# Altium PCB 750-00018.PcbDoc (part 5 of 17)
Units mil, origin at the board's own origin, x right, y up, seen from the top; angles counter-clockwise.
Board outline 7086.64 x 6299.21 mil, 8 copper layers (Top Layer, L2, L3, L4, L5, L6, L7, Bottom Layer), stack 60.6 mil thick; 1356 components, 1054 nets, 4851 pads, 4296 vias.
Unrouted connection lines stored in the file: 12.
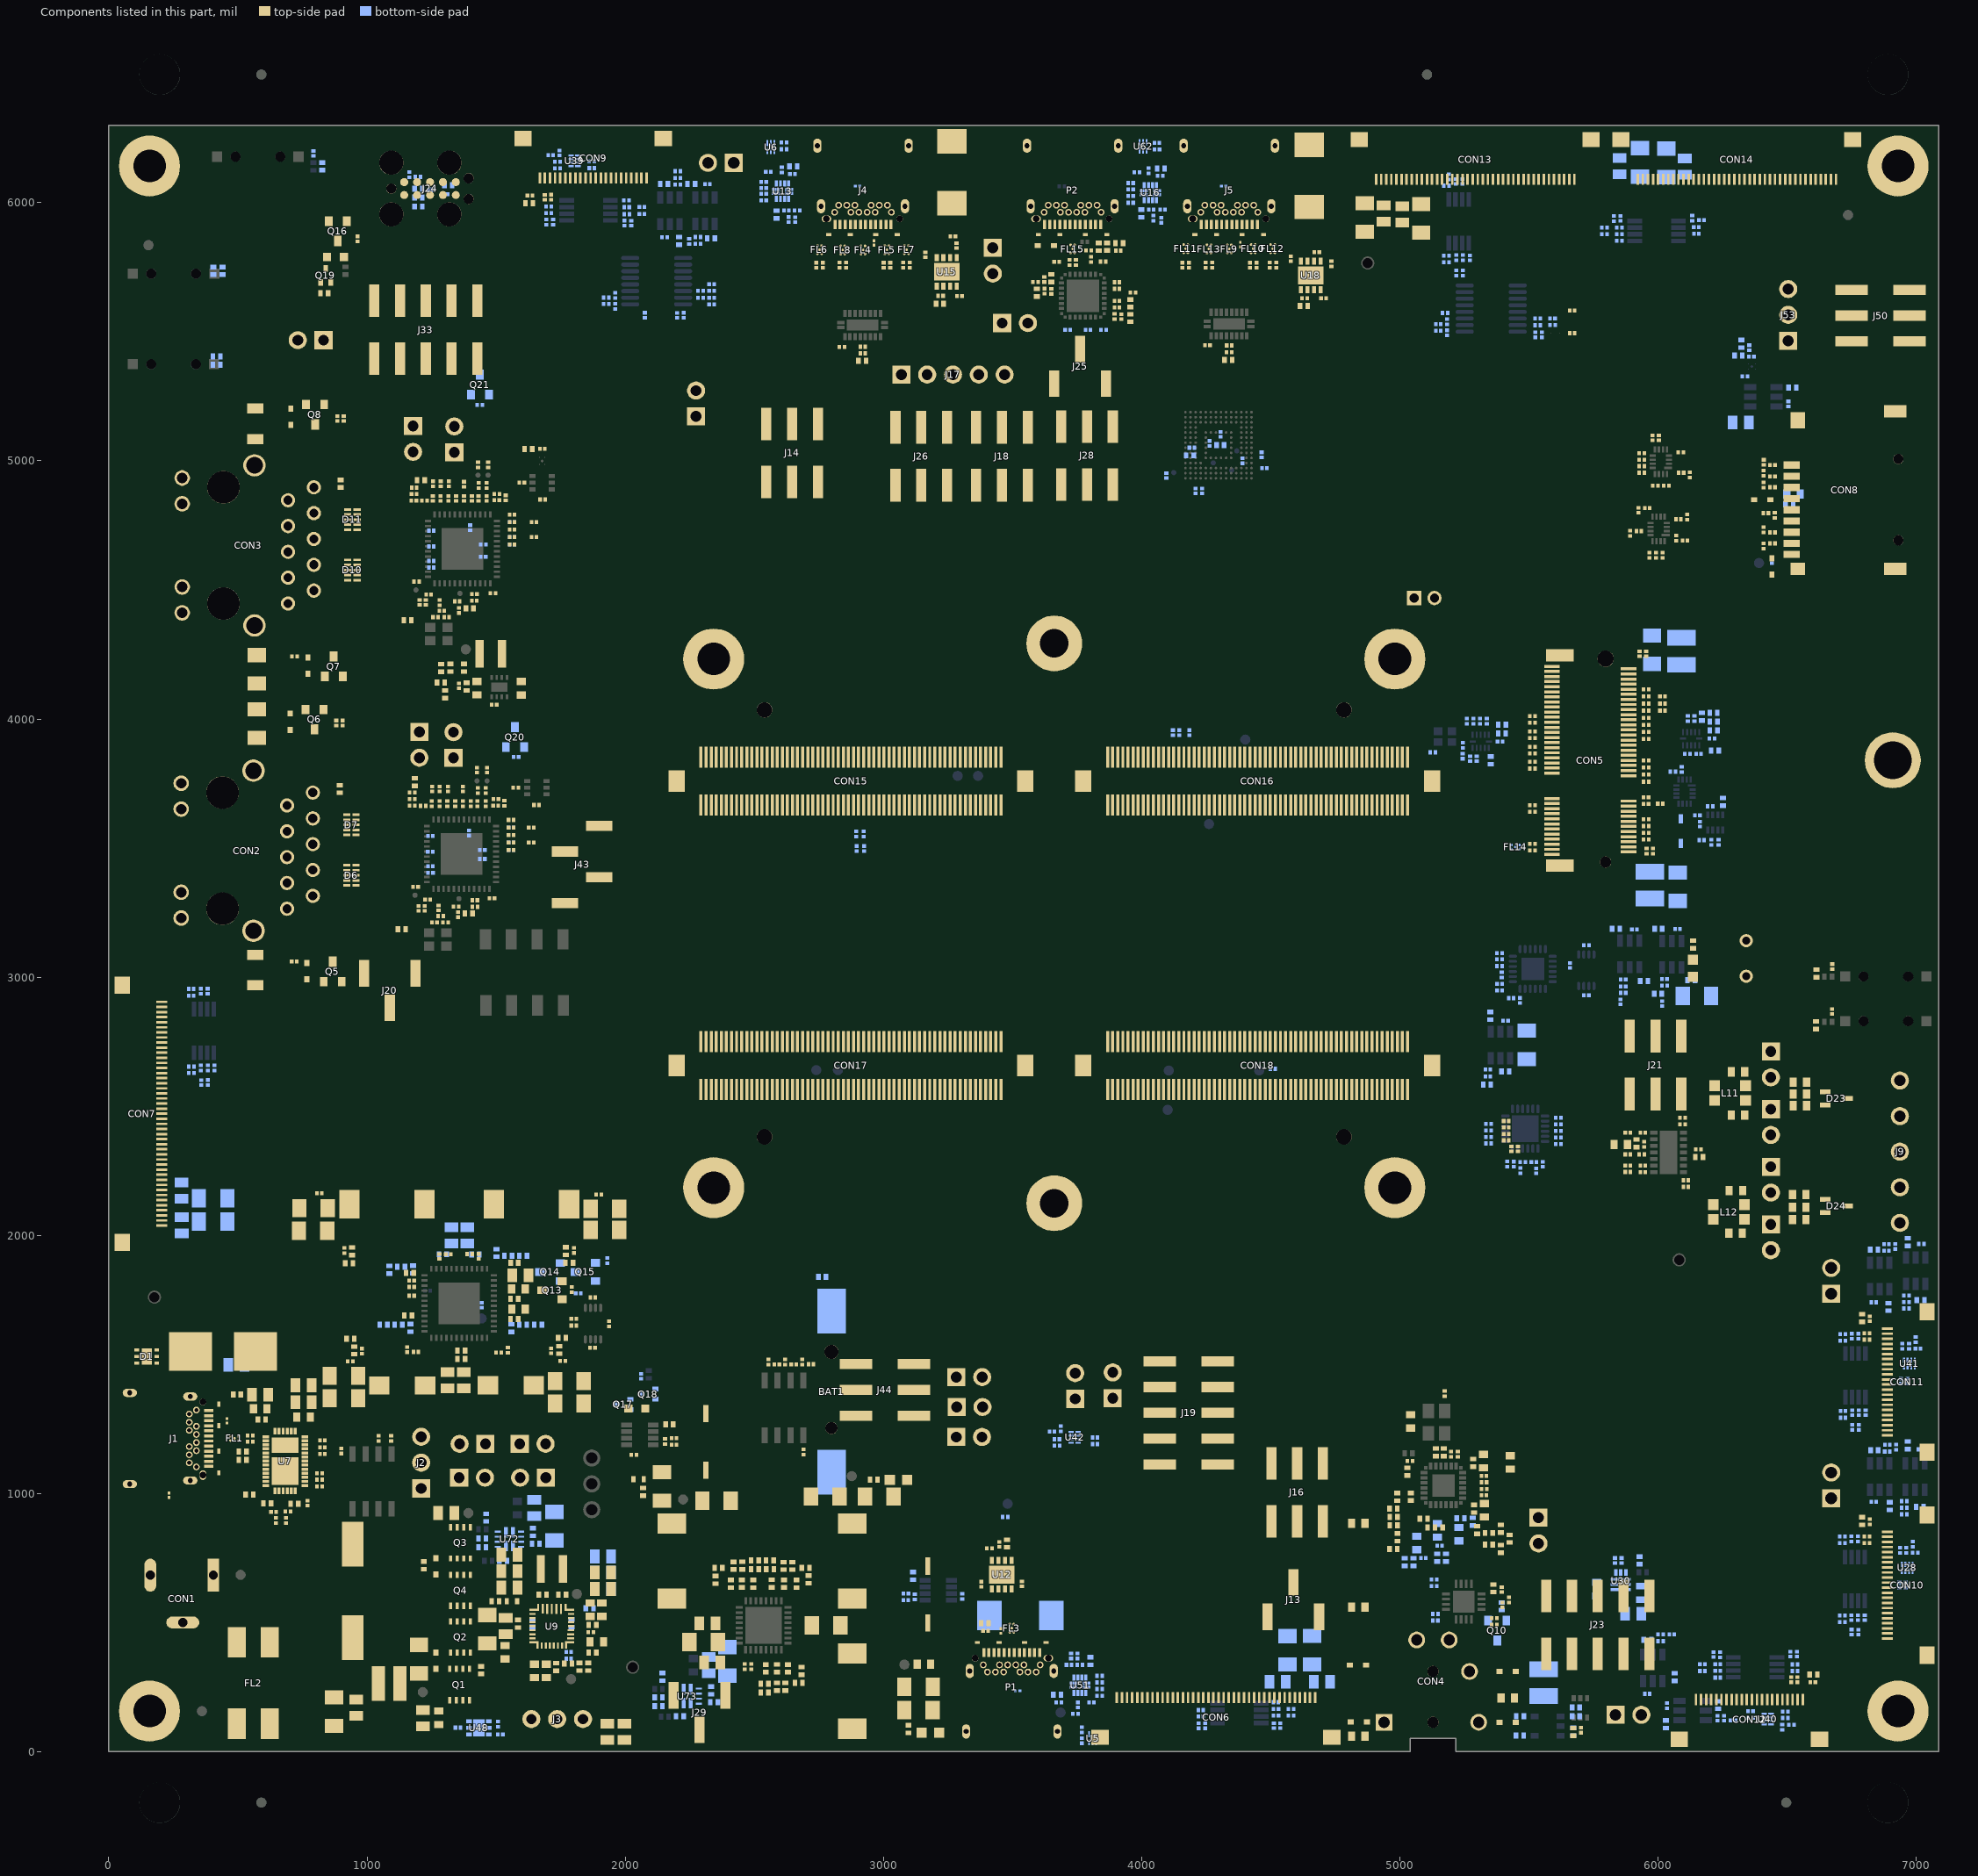
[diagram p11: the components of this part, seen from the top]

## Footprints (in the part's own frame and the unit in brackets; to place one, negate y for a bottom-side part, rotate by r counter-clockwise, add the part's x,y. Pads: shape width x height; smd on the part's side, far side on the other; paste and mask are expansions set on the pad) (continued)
"VQFN29, 4x4, Pitch 0.45 & 0.4mm, Height 1mm" [mm] "VQFN, 29 pin, 4mm x 4mm, Pitch 0.45 & 0.4mm, Height 1mm"
  rect 0.95x0.2 smd mask+0.051: 1(-1.725,1.6) 24(1.725,1.6)
  rect 0.2x0.7 smd mask+0.051: 1(-1.35,1.85) 9(-1.4,-1.85) 16(1.4,-1.85) 24(1.35,1.85)
  rect 0.6x0.2 smd mask+0.051: 2(-1.9,1.2) 3(-1.9,0.8) 4(-1.9,0.4) 5(-1.9,0) 6(-1.9,-0.4) 7(-1.9,-0.8) 8(-1.9,-1.2) 20(1.9,0) 21(1.9,0.4) 22(1.9,0.8) 23(1.9,1.2)
  rect 0.9x0.2 smd mask+0.051: 9(-1.75,-1.6) 16(1.75,-1.6)
  rect 0.2x0.6 smd mask+0.051: 10(-1,-1.9) 11(-0.6,-1.9) 12(-0.2,-1.9) 13(0.2,-1.9) 14(0.6,-1.9) 15(1,-1.9)
  rect 0.7x0.2 smd mask+0.051: 17(1.85,-1.2)
  rect 0.68x0.2 smd mask+0.051: 18(1.863,-0.8)
  rect 0.65x0.2 smd mask+0.051: 19(1.875,-0.4)
  rect 0.2x1 smd mask+0.051: 25(0.9,1.7) 26(0.45,1.7) 27(0,1.7) 28(-0.45,1.7)
  rect 0.2x0.95 smd mask+0.051: 29(-0.9,1.725)
  silkscreen extent -2.31,-2.31 2.31,2.31, body extent -2.06,-2.06 2.06,2.06, height 0.9
"VQFN-HR(9), 1.5mm x 2.0mm, Pitch 0.5mm, Height 1mm, SMD" [mm] "VQFN-HR(9), 1.5mm x 2.0mm, Pitch 0.5mm, Height 1mm"
  rect 0.75x0.3 smd paste-0.051 mask-0.051: 1(-0.625,0.25) 2(-0.625,-0.25) 3(-0.625,-0.75) 5(0.625,-0.25)
  rect 1.1x0.3 smd paste-0.051 mask-0.051: 4(0.45,-0.75) 6(0.45,0.25)
  rect 0.35x0.65 smd paste-0.051 mask-0.051: 7(0.5,0.925) 8(0,0.925) 9(-0.5,0.925)
  silkscreen extent -1.08,-1 1.08,1.32, body extent -0.75,-1 0.75,1, height 1.01
"VQFN-HR(12), 2.5mm x 2.0mm, Pitch 0.5mm & 0.7mm, Height 1mm" [mm] "VQFN-HR(12), 2.5mm x 2.0mm, Pitch 0.5mm & 0.7mm, Height 1mm"
  rect 1.05x0.4 smd mask+0.051: 1(-0.675,0.35) 2(-0.675,-0.35) 7(0.675,-0.35) 8(0.675,0.35)
  rect 0.2x0.6 smd mask+0.051: 3(-0.75,-1.15) 4(-0.25,-1.15) 5(0.25,-1.15) 6(0.75,-1.15) 9(0.75,1.15) 10(0.25,1.15) 11(-0.25,1.15) 12(-0.75,1.15)
  silkscreen extent -1.34,-1.57 1.34,1.57, body extent -1.05,-1.26 1.05,1.26, height 1
"VSON8, 3mm x 3mm, Height 1.0mm, SMD" [mm] "VSON, 8 Leads Body 3mm x 3mm, Pitch 0.65mm, Height 1.0mm, Thermal Pad 1.65mm x 2.4mm"
  rect 0.7x0.4 smd paste-0.051 mask-0.051: 1(-1.4,0.975) 2(-1.4,0.325) 3(-1.4,-0.325) 4(-1.4,-0.975) 5(1.4,-0.975) 6(1.4,-0.325) 7(1.4,0.325) 8(1.4,0.975)
  rect 1.75x2.5 smd paste-2539.97 mask-0.051: 9(0,0)
  silkscreen extent -1.5,-1.5 1.5,1.5, body extent -1.5,-1.5 1.5,1.5, height 1.01
"WQFN40, 6x4, Pitch 0.4mm, Height 0.8mm, SMD" [mm] "QFN, 40Leads, 6mm x 4mm, Pitch 0.4mm, Height 0.8mm"
  rect 0.65x0.3 smd paste-0.051 mask-0.051: 1(-2.925,1) 2(-2.925,0.6) 3(-2.925,0.2) 4(-2.925,-0.2) 5(-2.925,-0.6) 6(-2.925,-1) 20(2.925,-1) 21(2.925,-0.6) 22(2.925,-0.2) 23(2.925,0.2) 24(2.925,0.6) 25(2.925,1)
  rect 0.3x0.65 smd paste-0.051 mask-0.051: 7(-2.4,-1.925) 8(-2,-1.925) 9(-1.6,-1.925) 10(-1.2,-1.925) 11(-0.8,-1.925) 12(-0.4,-1.925) 13(0,-1.925) 14(0.4,-1.925) 15(0.8,-1.925) 16(1.2,-1.925) 17(1.6,-1.925) 18(2,-1.925) 19(2.4,-1.925) 26(2.4,1.925) 27(2,1.925) 28(1.6,1.925) 29(1.2,1.925) 30(0.8,1.925) 31(0.4,1.925) 32(0,1.925) 33(-0.4,1.925) 34(-0.8,1.925) 35(-1.2,1.925) 36(-1.6,1.925) 37(-2,1.925) 38(-2.4,1.925)
  rect 2.72x2.65 smd paste-2539.97 mask+0.051: 39(-0.965,0)
  rect 1.53x2.65 smd paste-2539.97 mask+0.051: 40(1.56,0)
  Top Layer region: -1.2,2.25 -1.2,1.6 -0.8,1.6 -0.8,2.25
  Top Layer region: -0.4,2.251 -0.4,1.601 0,1.601 0,2.251
  Top Layer region: 3.25,1 2.6,1 2.6,0.2 3.25,0.2
  Top Layer region: 3.25,-0.2 2.6,-0.2 2.6,-1 3.25,-1
  silkscreen extent -3.43,-2.47 3.43,2.47, body extent -3,-2 3,2, height 0.81
"WSON6, 2x2, SMD" [mm] "WSON, 6-Leads, Body 2x2mm, Height 0.8mm, Pitch 0.65mm"
  rect 0.55x0.4 smd paste-0.051 mask-0.051: 1(-0.975,0.65) 2(-0.975,0) 3(-0.975,-0.65) 4(0.975,-0.65) 5(0.975,0) 6(0.975,0.65)
  rect 1.1x1.7 smd paste-2.1 mask-0.051: 7(0,0)
  silkscreen extent -1.52,-1 1.35,1.01, body extent -1.01,-1 1.01,1, height 0.85
"WSON6_2x2, Height 0.8mm" [mm] "WSON, 6 pin, 2mm x 2mm, Height 0.8mm"
  rect 0.45x0.3 smd mask+0.051: 1(-0.975,0.65) 2(-0.975,0) 3(-0.975,-0.65) 4(0.975,-0.65) 5(0.975,0) 6(0.975,0.65)
  rect 1x1.6 smd paste-2.1 mask+0.051: 7(0,0)
  silkscreen extent -1.62,-1 1.35,1, body extent -1.01,-1 1.01,1, height 0.85
"Wurth, 74437336022" [mm] "Shielded Molded Inductor"
  rect 2x1.8 smd: 1(-2.25,0) 2(2.25,0)
  silkscreen extent -2.8,-2.75 2.75,2.75, body extent -2.85,-2.6 2.85,2.6, height 2.8
"Wurth, 74438336010" [mm] "Power Inductor, Shielded"
  rect 1.3x3.4 smd: 1(1.05,0) 2(-1.05,0)
  body extent -1.54,-1.5 1.46,1.5, height 2
"X2QFN12, 1.6mm x 1.6mm, Pitch 0.4mm, Height 0.4mm, SMD" [mm] "X2QFN12, 1.6mm x 1.6mm, Pitch 0.4mm, Height 0.4mm"
  rect 0.8x0.3 smd paste-0.051 mask-0.051: 1(-0.65,0.2) 2(-0.65,-0.2) 7(0.65,-0.2) 8(0.65,0.2)
  rect 0.3x0.6 smd paste-0.051 mask-0.051: 3(-0.6,-0.75) 4(-0.2,-0.75) 5(0.2,-0.75) 6(0.6,-0.75) 9(0.6,0.75) 10(0.2,0.75) 11(-0.2,0.75) 12(-0.6,0.75)
  silkscreen extent -1.2,-1.2 1.2,1.2, body extent -0.8,-0.8 0.8,0.8, height 0.41
"X2SON, Height 0.4mm" [mm] "X2SON, 6L, body 1.0x1.0mm, Height 0.4mm, Pitch 0.35mm"
  rect 0.6x0.17 smd mask+0.051: 1(-0.4,0.35) 2(-0.4,0) 3(-0.4,-0.35) 4(0.4,-0.35) 5(0.4,0) 6(0.4,0.35)
  silkscreen extent -0.83,-0.57 0.83,0.57, body extent -0.5,-0.5 0.5,0.5, height 0.41
X2SON-2#1 [mm] "X2SON, 2-Leads, 0.6mm x 0.3mm, Height 0.32mm"
  rect 0.28x0.25 smd mask+0.051: 1(-0.22,0) 2(0.22,0)
  silkscreen extent -0.49,-0.24 0.48,0.24, body extent -0.3,-0.15 0.3,0.15, height 0.27
X2SON-2#2 [mm] "X2SON, 2-Leads, 0.6mm x 0.3mm, Height 0.32mm"
  rect 0.28x0.25 smd mask+0.051: 1(-0.22,0)
  rect 0.28x0.25 smd mask+0: 2(0.22,0)
  silkscreen extent -0.49,-0.24 0.48,0.24, body extent -0.3,-0.15 0.3,0.15, height 0.27
"XFDFN8, 1.4x1.0, 0.4mm" [mm] "XFDFN, 8 pin, Body 1.4 mm x1.00mm, Height 0.4mm, Pitch 0.35mm"
  rect 0.53x0.2 smd mask+0.051: 1(-0.335,0.525) 2(-0.335,0.175) 3(-0.335,-0.175) 4(-0.335,-0.525) 5(0.335,-0.525) 6(0.335,-0.175) 7(0.335,0.175) 8(0.335,0.525)
  silkscreen extent -0.98,-0.77 0.73,0.77, body extent -0.53,-0.7 0.53,0.7, height 0.35

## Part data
BAT1: library part CMP-CON-130-00244-1.0, "CON, SMT, Battery Holder, CR1220", Manufacturer="Adam Tech", Manufacturer Part Number=BH-44F-5, Operating Temperature=-25C~85C
C1 C2 C94 C111 C112 C216 C218 C240 C251 C376 C378 C380 C382 C384 C386: library part CMP-CAP-502-00133-1.6, "CAP, SMT, 1206, MLCC, 10uF, 50V, X5R, 10%", Manufacturer=Murata, Manufacturer Part Number=GRM31CR61H106KA12, Operating Temperature=-55C~125C, Temp Coefficient=X5R, TOLERANCE=10%, Voltage=50V
C3 C50 C76 C110 C113 C215 C217 C219 C377 C379 C381 C383 C385: library part CMP-CAP-502-00105-1.7, "CAP, SMT, 0805, MLCC, 1uF, 50V, X7R, 5%,", Manufacturer=Yageo, Manufacturer Part Number=CC0805JKX7R9BB105, Operating Temperature=-55C~125C, Temp Coefficient=X7R, TOLERANCE=5%, Voltage=50V
C4 C9 C20 C96 C97: library part CMP-CAP-502-00209-1.12, "CAP, SMT, 0402, MLCC, 47nF, 25V, X7R, 10%", Manufacturer=Yageo, Manufacturer Part Number=CC0402KRX7R8BB473, Operating Temperature=-55C~125C, Temp Coefficient=X7R, TOLERANCE=10%, Voltage=25V
C5 C10 C13 C15 C17 C22 C59 C60 C62 C293 C306: library part CMP-CAP-502-00090-1.18, "CAP, SMT, 0402, MLCC, 22pF, 50V, C0G, 1%", Manufacturer=Murata, Manufacturer Part Number=GJM1555C1H220FB01D, Operating Temperature=-55C~125C, Temp Coefficient=C0G, TOLERANCE=1%, Voltage=50V
C6 C7 C11 C12 C23 C24 C35 C36 C44 C45 C52 C53 C68 C69 C244 C311: library part CMP-CAP-502-00015-1.9, "CAP, SMT, 1206, MLCC, 22uF, 10V, X7R,  20%", Manufacturer=Yageo, Manufacturer Part Number=CC1206MKX7R6BB226, Operating Temperature=-55C~125C, Temp Coefficient=X7R, TOLERANCE=20%, Voltage=10V
C8 C84 C85 C89 C99 C100 C102 C103 C104 C105 C106 C107 C117: library part CMP-CAP-502-00304-1.3, "CAP, SMT, 0805, MLCC, 10uF, 50V, X5R, 10%,", Manufacturer=Walsin, Manufacturer Part Number=0805X106K500, Operating Temperature=-55C~85C, Temp Coefficient=X5R, TOLERANCE=10%, Voltage=50V
C14: library part CMP-CAP-502-00188-1.13, "CAP, SMT, 0402, MLCC, 2.2nF, 25V, X7R, 10%", Manufacturer=Walsin, Manufacturer Part Number=0402B222K250, Operating Temperature=-55C~125C, Temp Coefficient=X7R, TOLERANCE=10%, Voltage=25V
C16 C18: library part CMP-CAP-502-00189-1.13, "CAP, SMT, 0402, MLCC, 3.3nF, 16V, X7R, 10%", Manufacturer=Yageo, Manufacturer Part Number=CC0402KPX7R7BB333, Operating Temperature=-55C~125C, Temp Coefficient=X7R, TOLERANCE=10%, Voltage=16V
C19 C21 C25 C79 C369: library part CMP-CAP-502-00063-1.17, "CAP, SMT, 0402, MLCC, 10nF, 50V, X7R, 10%", Manufacturer=Yageo, Manufacturer Part Number=CC0402KRX7R9BB103, Operating Temperature=-55C~125C, Temp Coefficient=X7R, TOLERANCE=10%, Voltage=50V
C26 C27 C31 C40 C48 C65 C73 C95 C101 C108 C193 C196 C200 C210 C231 C232 C233 C234 C245 C300 C304 C321 C327 C328 C333 C334 C343 C344 C349 C350 C356 C364 C365 C366: library part CMP-CAP-502-00055-1.18, "CAP, SMT, 0402, MLCC, 100nF, 50V, X5R, 10%", Manufacturer=Murata, Manufacturer Part Number=GRM155R61H104KE14, Operating Temperature=-55C~85C, Temp Coefficient=X5R, TOLERANCE=10%, Voltage=50V
C28 C29 C354 C355 C357 C358 C359 C360: library part CMP-CAP-502-00153-1.12, "CAP, SMT, 0201, MLCC, 220nF, 10V, X5R, 20%", Manufacturer="Taiyo Yuden", Manufacturer Part Number=LMK063BJ224MP-F, Operating Temperature=-55C~85C, Temp Coefficient=X5R, TOLERANCE=20%, Voltage=10V
C30 C39 C46 C63 C291 C298: library part CMP-CAP-502-00443-1.1, "CAP, SMT, 0805, MLCC, 22uF, 25V, X5R, 20%", Manufacturer=Murata, Manufacturer Part Number=GRM21BR61E226ME44L, Operating Temperature=-55C~85C, Temp Coefficient=X5R, TOLERANCE=20%, Voltage=25V
C32 C34 C42 C43 C49 C51 C66 C67 C71 C72 C74 C87 C120 C127 C135 C146 C153 C161 C171 C173 C174 C177 C179 C181 C183 C186 C188 C190 C198 C222 C226 C227 C228 C229 C241 C242 C248 C249 C252 C253 C255 C256 C257 C258 C259 C260 C261 C262 C263 C267 C268 C269 C272 C274 C275 C280 C282 C284 C287 C288 C294 C295 C302 C309 C312 C313 C314 C315 C316 C317 C318 C319 C320 C322 C324 C336 C338 C367 C368 C374 C375 C387 C391 C392 C393 C394 C397 C398 C401 C402 C405 C406 C409 C410 C413 C414: library part CMP-CAP-502-00139-1.20, "CAP, SMT, 0201, MLCC, 0.1uF, 10V, X5R, 10%", Manufacturer=Murata, Manufacturer Part Number=GRM033R61A104KE15#, Operating Temperature=-55C~85C, Temp Coefficient=X5R, TOLERANCE=10%, Voltage=10V
C33 C37 C38 C55 C56 C61 C64 C388 C389: library part CMP-CAP-502-00058-1.17, "CAP, SMT, 0402, MLCC, 4.7nF, 25V, X7R, 10%", Manufacturer=Walsin, Manufacturer Part Number=0402B472K250, Operating Temperature=-55C~125C, Temp Coefficient=X7R, TOLERANCE=10%, Voltage=25V
C41 C47 C58 C70: library part CMP-CAP-502-00345-1.6, "CAP, SMT, 0201, MLCC, 120pF, 50V, X7R, 5%", Manufacturer=Yageo, Manufacturer Part Number=CC0201JRX7R9BB121, Operating Temperature=-55C~125C, Temp Coefficient=X7R, TOLERANCE=5%, Voltage=50V
C54: library part CMP-CAP-502-00019-1.13, "CAP, SMT, 0603, MLCC, 3.3uF, 10V, X5R, 10%", Manufacturer=Walsin, Manufacturer Part Number=0603X335K100CT, Operating Temperature=-55C~85C, Temp Coefficient=X5R, TOLERANCE=10%, Voltage=10V
C57 C90 C91 C192 C195 C199 C292 C305 C307: library part CMP-CAP-502-00211-1.9, "CAP, SMT, 0603, MLCC, 10uF, 25V, X5R, 20%", Manufacturer=Yageo, Manufacturer Part Number=CC0603MRX5R8BB106, Operating Temperature=-55C~85C, Temp Coefficient=X5R, TOLERANCE=20%, Voltage=25V
C75 C80 C81 C172 C176 C178 C182 C185 C187 C191 C271 C273 C281 C283 C289 C290 C310 C323 C325 C337 C339: library part CMP-CAP-502-00207-1.15, "CAP, SMT, 0402, MLCC, 10uF, 10V, X5R, 20%", Manufacturer=Yageo, Manufacturer Part Number=CC0402MRX5R6BB106, Operating Temperature=-55C~85C, Temp Coefficient=X5R, TOLERANCE=20%, Voltage=10V
C77 C98 C116: library part CMP-CAP-502-00129-1.6, "CAP, SMT, 0805, MLCC, 4.7uF, 50V, X5R, 10%", Manufacturer=Murata, Manufacturer Part Number=GRM21BR61H475KE51, Operating Temperature=-55C~85C, Temp Coefficient=X5R, TOLERANCE=10%, Voltage=50V
C78 C86 C297: library part CMP-CAP-502-00366-1.5, "CAP, SMT, 0603, MLCC, 100nF, 50V, X7R, 10%", Manufacturer=Murata, Manufacturer Part Number=GCM188R71H104KA57D, Operating Temperature=-55C~125C, Temp Coefficient=X7R, TOLERANCE=10%, Voltage=50V
C82 C83: library part CMP-CAP-502-00290-1.10, "CAP, SMT, 0402, MLCC, 330pF, 50V, X7R, 10%,", Manufacturer=Yageo, Manufacturer Part Number=CC0402KRX7R9BB331, Operating Temperature=-55C~125C, Temp Coefficient=X7R, TOLERANCE=10%, Voltage=50V
C88 C92 C109 C246 C299 C329 C330 C335 C340 C345 C346 C351 C352 C370 C372: library part CMP-CAP-502-00061-1.21, "CAP, SMT, 0402, MLCC, 1.0nF, 50V, C0G, NP0, 5%", Manufacturer=Murata, Manufacturer Part Number=GRM1555C1H102JA01#, Operating Temperature=-55C~125C, Temp Coefficient="C0G, NP0", TOLERANCE=5%, Voltage=50V
C93: library part CMP-CAP-502-00212-1.9, "CAP, SMT, 0603, MLCC, 4.7µF, 16V, X5R, 10%", Manufacturer=Yageo, Manufacturer Part Number=CC0603KRX5R7BB475, Operating Temperature=-55C~85C, Temp Coefficient=X5R, TOLERANCE=10%, Voltage=16V
C114: library part CMP-CAP-502-00215-1.9, "CAP, SMT, 0603, MLCC, 47nF, 25V, X7R, 10%", Manufacturer=Yageo, Manufacturer Part Number=CC0603KRX7R8BB473, Operating Temperature=-55C~125C, Temp Coefficient=X7R, TOLERANCE=10%, Voltage=25V
C115: library part CMP-CAP-502-00120-1.9, "CAP, SMT, Radial Can, Electrolytic, 100uF, 50V, NA, 20%,", Manufacturer=Kemet, Manufacturer Part Number=EDT107M050A9PAA, Operating Temperature=-40C~125C, Temp Coefficient=NA, TOLERANCE=20%, Voltage=50V
C118 C119 C126 C131 C134 C141 C144 C145 C152 C157 C160 C167 C223 C224 C225 C230 C235 C236 C237 C238 C301 C361 C390 C395 C396 C399 C400 C403 C404 C407 C408 C411 C412 C415 C416: library part CMP-CAP-502-00077-1.18, "CAP, SMT, 0201, MLCC, 1uF, 10V, X5R, 20%", Manufacturer=Murata, Manufacturer Part Number=GRM033R61A105ME15D, Operating Temperature=-55C~85C, Temp Coefficient=X5R, TOLERANCE=20%, Voltage=10V
C121 C128 C132 C133 C136 C137 C147 C154 C158 C159 C162 C163 C247 C326 C331 C332 C341 C342 C347 C348 C362 C363 C371 C373: library part CMP-CAP-502-00122-1.18, "CAP, SMT, 0201, MLCC, 1000pF, 25V, X7R, 10%", Manufacturer=Murata, Manufacturer Part Number=GRM033R71E102KA01#, Operating Temperature=-55C~125C, Temp Coefficient=X7R, TOLERANCE=10%, Voltage=25V
C122 C129 C130 C148 C155 C156: library part CMP-CAP-502-00100-1.15, "CAP, SMT, 0201, MLCC, 100pF, 50V, C0G, NPO, 5%", Manufacturer=Murata, Manufacturer Part Number=GRM0335C1H101JA01#, Operating Temperature=-55C~125C, Temp Coefficient="C0G, NP0", TOLERANCE=5%, Voltage=50V
C123 C149: library part CMP-CAP-502-00016-1.19, "CAP, SMT, 0201, MLCC, 22pF, 50V, C0G, 1%", Manufacturer=Murata, Manufacturer Part Number=GRM0335C1H220FA01#, Operating Temperature=-55C~125C, Temp Coefficient=C0G, TOLERANCE=1%, Voltage=50V
C124 C125 C150 C151: library part CMP-CAP-502-00172-1.11, "CAP, SMT, 0201, MLCC, 470pF, 25V, C0G, NP0, 5%", Manufacturer=Murata, Manufacturer Part Number=GRM0335C1E471JA01#, Operating Temperature=-55C~125C, Temp Coefficient="C0G, NP0", TOLERANCE=5%, Voltage=25V
C138 C164: library part CMP-CAP-502-00089-1.18, "CAP, SMT, 0402, MLCC, 220nF, 16V, X7R, 10%", Manufacturer=Yageo, Manufacturer Part Number=CC0402KRX7R5BB224, Operating Temperature=-55C~125C, Temp Coefficient=X7R, TOLERANCE=10%, Voltage=16V
C139 C165 C180 C189 C285 C286: library part CMP-CAP-502-00031-1.16, "CAP, SMT, 0201, MLCC, 10nF, 10V, X7R, 10%", Alt. Manufacturer=Murata, Alt. Manufacturer Part Number=GRM033R71A103K, Manufacturer=Walsin, Manufacturer Part Number=0201B103K100CT, Operating Temperature=-55C~125C, Temp Coefficient=X7R, TOLERANCE=10%, Voltage=10V
C140 C166: library part CMP-CAP-502-00024-1.8, "CAP, SMT, 1206, MLCC, 1000pF, 2kV, X7R, 10%", Manufacturer=Yageo, Manufacturer Part Number=CC1206KKX7RDBB102, Operating Temperature=-55C~125C, Temp Coefficient=X7R, TOLERANCE=10%, Voltage=2kV
C142 C168: library part CMP-CAP-502-00165-1.11, "CAP, SMT, 0201, MLCC, 27pF, 25V, C0G, 2%", Manufacturer=Murata, Manufacturer Part Number=GJM0335C1E270GB01#, Operating Temperature=-55C~125C, Temp Coefficient=C0G, TOLERANCE=2%, Voltage=25V
C143 C169: library part CMP-CAP-502-00030-1.14, "CAP, SMT, 0201, MLCC, 33pF, 25V, C0G, 5%", Alt. Manufacturer=Murata, Alt. Manufacturer Part Number=GRM0335C1E330JA01, Manufacturer=Walsin, Manufacturer Part Number=0201N330J250LT, Operating Temperature=-55C~125C, Temp Coefficient=C0G, TOLERANCE=5%, Voltage=25V
C170 C175 C184: library part CMP-CAP-502-00074-1.13, "CAP, SMT, 7343, Tantalum Polymer, 150uF, 16V, 20%", Manufacturer=Panasonic, Manufacturer Part Number=16TQC150MYF, Operating Temperature=-55C~105C, Temp Coefficient=NA, TOLERANCE=20%, Voltage=16V
C194 C197 C206 C208: library part CMP-CAP-502-00277-1.7, "CAP, SMT, 0402, MLCC, 1.0uF, 16V, X5R, 10%", Manufacturer=Yageo, Manufacturer Part Number=CC0402KRX5R7BB105, Operating Temperature=-55C~85C, Temp Coefficient=X5R, TOLERANCE=10%, Voltage=16V
C201 C204: library part CMP-CAP-502-00175-1.15, "CAP, SMT, 0402, MLCC, 220pF, 50V, C0G, NP0, 5%,", Manufacturer=Murata, Manufacturer Part Number=GRM1555C1H221JA01#, Operating Temperature=-55C~125C, Temp Coefficient="C0G, NP0", TOLERANCE=5%, Voltage=50V
C202 C203: library part CMP-CAP-502-00075-1.10, "CAP, SMT, 0603, MLCC, 47uF, 6.3V, X5R, 20%", Manufacturer=Murata, Manufacturer Part Number=GRM188R60J476ME15D, Operating Temperature=-55C~85C, Temp Coefficient=X5R, TOLERANCE=20%, Voltage=6.3V
C205 C239 C250: library part CMP-CAP-502-00283-1.6, "CAP, SMT, 1210, MLCC, 100uF, 16V, X5R, 20%,", Manufacturer=KEMET, Manufacturer Part Number=C1210C107M4PACTU, Operating Temperature=-55C~85C, Temp Coefficient=X5R, TOLERANCE=20%, Voltage=16V
C207: library part CMP-CAP-502-00198-1.12, "CAP, SMT, 0402, MLCC, 2.2uF, 10V, X7S, 10%", Manufacturer=Murata, Manufacturer Part Number=GRM155C71A225KE11#, Operating Temperature=-55C~125C, Temp Coefficient=X7S, TOLERANCE=10%, Voltage=10V
C209 C211 C213 C214 C303: library part CMP-CAP-502-00052-1.19, "CAP, SMT, 0402, MLCC, 15pF, 50V, C0G, NP0, 5%", Manufacturer=Murata, Manufacturer Part Number=GRM1555C1H150JA01, Operating Temperature=-55C~125C, Temp Coefficient="C0G, NP0", TOLERANCE=5%, Voltage=50V
C212 C276: library part CMP-CAP-502-00439-1.2, "CAP, SMT, 0402, MLCC, 10uF, 6.3V, X5R, 20%", Manufacturer=Murata, Manufacturer Part Number=GRM155R60J106ME15#, Operating Temperature=-55C~85C, Temp Coefficient=X5R, TOLERANCE=20%, Voltage=6.3V
C220 C221 C254 C308 C353: library part CMP-CAP-502-00156-1.14, "CAP, SMT, 0402, MLCC, 4.7uF, 10V, X5R, 10%", Manufacturer="Samsung Electro-Mechanics", Manufacturer Part Number=CL05A475KP5NRNC, Operating Temperature=-55C~85C, Temp Coefficient=X5R, TOLERANCE=10%, Voltage=10V
C243: library part CMP-CAP-502-00147-1.8, "CAP, TH, Radial Can, Electrolytic, 220uF, 25V, NA, 20%,", Manufacturer=Nichicon, Manufacturer Part Number=UHE1E221MPD1TD, Operating Temperature=-40C~105C, Temp Coefficient=NA, TOLERANCE=20%, Voltage=25V
C264 C277: library part CMP-CAP-502-00203-1.9, "CAP, SMT, 0603, MLCC, 4.7nF, 50V, X7R, 5%", Manufacturer=Walsin, Manufacturer Part Number=0603B472J500CT, Operating Temperature=-55C~125C, Temp Coefficient=X7R, TOLERANCE=5%, Voltage=50V
C265 C266 C278 C279: library part CMP-CAP-502-00204-1.9, "CAP, SMT, 0603, MLCC, 100pF, 50V, NP0, 5%", Manufacturer=Walsin, Manufacturer Part Number=0603N101J500CT, Operating Temperature=-55C~125C, Temp Coefficient=NP0, TOLERANCE=5%, Voltage=50V
C270: library part CMP-CAP-502-00372-1.5, "CAP, SMT, 0201, MLCC, 47nF, 10V, X5R, 10%", Manufacturer=Murata, Manufacturer Part Number=GRM033R61A473KE84#, Operating Temperature=-55C~85C, Temp Coefficient=X5R, TOLERANCE=10%, Voltage=10V
C296: library part CMP-CAP-502-00042-1.23, "CAP, SMT, 0201, MLCC, 10pF, 25V, C0G, NP0, 2%", Alt. Manufacturer=Walsin, Alt. Manufacturer Part Number=0201N100G250, Manufacturer=Murata, Manufacturer Part Number=GJM0335C1E100GB01#, Operating Temperature=-55C~125C, Temp Coefficient="C0G, NP0", TOLERANCE=2%, Voltage=25V
C417 C418: library part CMP-CAP-502-00278-1.7, "CAP, SMT, 0402, MLCC, 0.1uF, 25V, X7R, 10%", Manufacturer=Yageo, Manufacturer Part Number=CC0402KRX7R8BB104, Operating Temperature=-55C~125C, Temp Coefficient=X7R, TOLERANCE=10%, Voltage=25V
C419 C421: library part CMP-CAP-502-00216-1.5, "CAP, SMT, 0805, MLCC, 1uF, 25V, X7R, 10%", Manufacturer=Yageo, Manufacturer Part Number=CC0805KKX7R8BB105, Operating Temperature=-55C~125C, Temp Coefficient=X7R, TOLERANCE=10%, Voltage=25V
C420 C422: library part CMP-CAP-502-00214-1.6, "CAP, SMT, 1206, MLCC, 10uF, 25V, X7R, 10%", Manufacturer=Yageo, Manufacturer Part Number=CC1206KKX7R8BB106, Operating Temperature=-55C~125C, Temp Coefficient=X7R, TOLERANCE=10%, Voltage=25V
C423: library part CMP-CAP-502-00106-1.13, "CAP, SMT, 0201, MLCC, 100nF, 10V, X7S, 10%", Manufacturer=Murata, Manufacturer Part Number=GRM033C71A104KE14#, Operating Temperature=-55C~125C, Temp Coefficient=X7S, TOLERANCE=10%, Voltage=10V
CON1: library part CMP-CON-130-00260-1.0, "CON, TH, Power jack, DIP/90, PHY=2mm, Black, DC12V/2A", Manufacturer=SH, Manufacturer Part Number=DC-005-2.0, Operating Temperature=-40C~70C, Voltage=DC12V/2A
CON2 CON3: library part CMP-CON-130-00297-1.0, "CON, TH, 2.54 pitch, 1x1, RJ45 with LED", Manufacturer=Kingconn, Manufacturer Part Number=7RJ45-F0-0332, Operating Temperature=-40C~85C
CON4: library part CMP-CON-130-00156-1.5, "CON, TH, 3.5mm AUDIO JACK, body 14 x 10.2 x 5mm", Manufacturer="CUI Devices", Manufacturer Part Number=SJ-43515TS, Operating Temperature=-25C~85C, Voltage=16V
CON5: library part CMP-CON-130-00023-1.15, "CON, SMT, M.2 Key-E, 67pins, 0.5mm, Height 4.1mm", Manufacturer=JAE, Manufacturer Part Number=SM3ZS067U410AER1000
CON6 CON13 CON14: library part CMP-CON-130-00233-1.0, "CON, SMT, FFC/FPC, 1x40, 0.5mm pitch, Right Angle, Notched Flex Cable", Manufacturer="Omron Electronics", Manufacturer Part Number=XF2M-4015-1A, Operating Temperature=-30C~85C, Voltage=50V
CON7: library part CMP-CON-130-00245-1.0, "CON, SMT, FFC/FPC, 1x45, 0.5mm pitch, Right Angle, Notched Flex Cable", Manufacturer="Omron Electronics", Manufacturer Part Number=XF2M-4515-1A, Operating Temperature=-30C~85C, Voltage=50V
CON8: library part CMP-CON-130-00113-1.3, "CON, SMT, Micro SD push type, SMT, 9P, Shielding", Manufacturer=Kingconn, Manufacturer Part Number=7MSDP-BA-1016, Operating Temperature=-40C~85C, Voltage=100V
CON9 CON10 CON11 CON12: library part CMP-CON-130-00277-1.0, "CON, SMT, FFC/FPC, 1x22, 0.5mm pitch, Right Angle,  Dual Contact", Manufacturer=Omron, Manufacturer Part Number=XF2M-2215-1A, Operating Temperature=-30C~85C, Voltage=50V
CON15 CON16 CON17 CON18: library part CMP-CON-130-00271-1.1, "CON, SMT, Board to Board, Plug, 2x120, 0.5mm,", Manufacturer=Kyocera, Manufacturer Part Number=145046120640868+, Operating Temperature=-25C~85C
D1: library part CMP-DIO-504-00077-1.1, "DIO, SMT, WSON-6, TVS, 22V Flat-Clamp Surge Protection", Manufacturer=TI, Manufacturer Part Number=TVS2200DRVR, Operating Temperature=-40C~125C, Voltage Forward=0.5V
D2 D3 D14 D15 D16 D17 D26 D29: library part CMP-DIO-504-00078-1.1, "DIO, SMT, X2SON-2, TVS for ESD Protection, 3.6V, Air 17kV, Contact 15kV, 0.18pF", Manufacturer="Texas Instruments", Manufacturer Part Number=TPD1E01B04DPLT, Operating Temperature=-40C~125C
D4 D5: library part CMP-DIO-504-00047-1.4, "DIO, SMT, SOD523, Zener, 300 mW, 12 V", Current="5 mA", Current Reverse="100nA @ 8V", Manufacturer="Diodes Inc.", Manufacturer Part Number=BZT52C12T, Operating Temperature=-65C~150C, Voltage Forward="900mV @ 10mA"
D6 D7 D10 D11: library part CMP-DIO-504-00035-1.4, "DIO, SMT, DFN2510A-10, TVS Array, USB2 USB3, 5.5V, 4A", Current=4A, Manufacturer=Nexperia, Manufacturer Part Number=IP4292CZ10-TBR,115, Operating Temperature=-40C~85C, Voltage Forward=0.7V, Voltage Reverse=NA
D8 D9 D12 D13 D18 D19 D20 D21 D25 D27 D28: library part CMP-DIO-504-00043-1.4, "DIO, SMT, SOD−523, TVS, Bidirictionsl, ESD Suppressors", Breakdown Voltage=7.8V, Current=NA, Manufacturer=ONSemiconductor, Manufacturer Part Number=ESD5B5.0ST1G, Operating Temperature=-55C~150C
D22: library part CMP-DIO-504-00044-1.2, "DIO, SMT, SOD323, Schottky, 0.24V, 20mA, 20V,", Current=10mA, Manufacturer=ONSemiconductor, Manufacturer Part Number=NSR0320MW2T1G, Operating Temperature=-55C~150C, Voltage Forward=0.24V, Voltage Reverse=20V
D23 D24: library part CMP-DIO-504-00079-1.1, "DIO, SMT, SC70-3, TVS for ESD Protection, 24V, Air 30kV, Contact 30kV, 5pF", Manufacturer="Texas Instruments", Manufacturer Part Number=ESD2CAN24DCKRQ1, Operating Temperature=-55C~150C
F1: library part CMP-FUS-509-00019-1.3, "FUS, SMT, Fuse and Holder, Fast Blow, 10A", Hold Current=10A, Manufacturer=Littelfuse, Manufacturer Part Number=0154010.DR, Operating Temperature=-55C~125C, Voltage=125V
FB1 FB2 FB3 FB4 FB15 FB16 FB17 FB18: library part CMP-FB-505-00016-1.1, "FB, SMT, 0402, 220 Ohm @ 100MHz, 250mA, 1.0 Ohm", Current=250mA, DC Resistance="1.0 Ohm", Impedance@Frequency="220 Ohm @ 100MHz", Manufacturer=Murata, Manufacturer Part Number=BLM15HB221SN1, Operating Temperature=-55C~125C
FB5 FB6 FB8: library part CMP-FB-505-00005-1.3, "FB, SMT, 0402, 120 Ohm @ 100MHz, 450mA, 190 mOhm,", Current=550mA, DC Resistance="190 mOhm", Impedance@Frequency="120 Ohm @ 100MHz", Manufacturer=Murata, Manufacturer Part Number=BLM15AG121SN1, Operating Temperature=-55C~125C
FB9: library part CMP-FB-505-00011-1.1, "FB, SMT, 0603, 220 Ohm @ 100 MHz, 1.4A, 100 mOhm", Current=1.4A, DC Resistance="100 mOhm", Impedance@Frequency="220 Ohm @ 100MHz", Manufacturer=Murata, Manufacturer Part Number=BLM18PG221SH1#, Operating Temperature=-55C~125C
FB13 FB14: library part CMP-FB-505-00006-1.4, "FB, SMT, 0402, 120 Ohm @ 100MHz, 1.3A, 90 mOhm", Current=1.3A, DC Resistance="90 mOhm", Impedance@Frequency="120 Ohm @ 100MHz", Manufacturer=Murata, Manufacturer Part Number=BLM15PD121SN1#, Operating Temperature=-55C~125C
FL1 FL3 FL4 FL5 FL6 FL7 FL8 FL9 FL10 FL11 FL12 FL13 FL14 FL15: library part CMP-FLT-507-00012-1.1, "FLT, SMT, WLCSP5, Common Mode EMI Filters", Manufacturer=Nexperia, Manufacturer Part Number=PCMF1USB3S, Operating Temperature="-40ºC ~ +125ºC", Supply Current=NO
FL2: library part CMP-FLT-507-00010-1.1, "FLT, SMT, body 9x7mm, 100MHz, 700 Ohm", Frequency (Center)="10 to 55 Hz", Manufacturer=Maglayers, Manufacturer Part Number=MCM-9070F-701, Operating Temperature=-40C~155C
J1 J4 J5 P1 P2: library part CMP-CON-130-00120-1.4, "CON, TH, USB-C Type, 24 PIN, DIP+SMT 90d", Manufacturer=Kingconn, Manufacturer Part Number=7USB31-F0-0029, Operating Temperature=-25C~85C
J2 J53: library part CMP-CON-130-00042-1.3, "CON, TH, Header, 3 pin, 2.54mm pitch, Male, Vertical", Manufacturer=Kingmate, Manufacturer Part Number=S110-S-03-2-60/25/30, Operating Temperature=-40C~105C, Voltage=1000V
J3: library part CMP-CON-130-00122-1.3, "CON, TH, Wire Header, 1x3, 2.54mm", Manufacturer=Molex, Manufacturer Part Number=22112032, Voltage=500V
J6 J7 J8 J10 J11 J12 J22 J27 J30 J31 J32 J34 J35 J36 J37 J38 J39 J40 J41 J42 J47 J51: library part CMP-CON-130-00034-1.8, "CON, TH, Header, 2 pin, 2.54mm pitch, Male, Vertical", Manufacturer=Kingmate, Manufacturer Part Number=S110-S-02-2-60/25/30, Operating Temperature=-40C~105C, Voltage=1000V
J9: library part CMP-CON-130-00106-1.1, "CON, TH, Fixed Terminal Blocks, 5 pin, 3.5mm pitch, right angle", Manufacturer=KINGMATE, Manufacturer Part Number=ED350V-05P, Operating Temperature=-40C~130C
J13 J20 J25 J29: library part CMP-CON-130-00220-1.3, "CON, SMT, Header, 1X3 pins, 2.54mm pitch, Male, Vertical", Manufacturer=Kingmate, Manufacturer Part Number=S113-A-03-2-60/33-F0, Operating Temperature=-40C~105C
J14 J16 J18 J21 J26 J28 J44 J50: library part CMP-CON-130-00117-1.2, "CON, SMT, Header, 2X3 pins, 2.54mm pitch, Male, Vertical", Manufacturer=Kingmate, Manufacturer Part Number=S123-T-06-2-60/33-F0, Operating Temperature=-40C~105C
J17: library part CMP-CON-130-00129-1.2, "CON, TH, Vertical TH, 2P54MM-1X5, Male Pin, 1x5", Manufacturer=Kingmate, Manufacturer Part Number=S110-S-05-2-60/25/30, Operating Temperature=-40C~105C
J19 J23 J33: library part CMP-CON-130-00238-1.0, "CON, SMT, Header, 2X5 pins, 2.54mm pitch, Male, Vertical", Manufacturer=Kingmate, Manufacturer Part Number=S123-T-10-2-60/33-F0, Operating Temperature=-40C~105C
J24: library part CMP-CON-130-00027-1.7, "CON, SMT/TH, Tag-Connect 2050, ,2 x5 , 3.175mm, PCB Footprint only", Manufacturer=Tag-Connect, Manufacturer Part Number=TC2050-IDC-NL
J43: library part CMP-CON-130-00242-1.0, "CON, SMT, Header, 1X4 pins, 2.54mm pitch, Male, Vertical", Manufacturer=Kingmate, Manufacturer Part Number=S113-B-04-2-58/38-F0, Operating Temperature=-40C~105C
J45 J46 J48 J49: library part CMP-CON-130-00304-1.2, "CON, TH, 1x2, Vertical Header with Friction Lock, 2.54mm", Manufacturer=Molex, Manufacturer Part Number=1718561002, Operating Temperature=-40C~105C, Voltage=500V
J52: library part CMP-CON-130-00282-1.0, "CON, TH, Vertical  Header, 2P0MM-1X2, Male Pin, 1x2, 2.0mm, PHY 0.5mm", Manufacturer=Kingmate, Manufacturer Part Number=Q110-S-02-2-38/20/30-E1, Operating Temperature=-40C~105C
JMP7 JMP8 JMP10 JMP11 JMP31 JMP32 JMP34 JMP35 JMP36 JMP40 JMP41 JMP53: library part CMP-CON-130-00121-1.11, "CON, TH, Pin header jumper CAP open type, Pitch 2.54mm,", Alt. Manufacturer=Any, Manufacturer=Kingmate, Manufacturer Part Number=S901D-1-1-E1, Operating Temperature=-40C~105C
L1 L2 L3 L6 L7: library part CMP-IND-511-00140-1.2, "IND, SMT, 9.2x7.5mm, Power Inductor, Shielded, 4.7 uH, 3A, 45 mOhm", Current=3A, DC Resistance="45 mOhm", Manufacturer=Maglayers, Manufacturer Part Number=MSCDRI-7025AL-4R7M-F, Operating Temperature=-40C~125C, Test Frequency=1MHz, TOLERANCE=20%
L4 L5: library part CMP-IND-511-00061-1.4, "IND, SMT, 5030, Sheilded, 2,2uH, 4.9A, 100KHz, 35mOhm", Current=4.9A, DC Resistance=35mOhm, Manufacturer=Wurth, Manufacturer Part Number=74437336022, Operating Temperature=-40C~125C, Test Frequency=100KHz, TOLERANCE=30%
L8 L13: library part CMP-IND-511-00047-1.6, "IND, SMT, 3030, Power Inductor, Shielded, 1uH, 3.3A, 20 %, 1MHz, 50 mOhm", Current=3.3A, DC Resistance="50 mOhm", Manufacturer="Taiyo Yuden", Manufacturer Part Number=MDMK3030T1R0MM, Operating Temperature=-40C~125C, TOLERANCE="20 %"
L9: library part CMP-IND-511-00074-1.3, "IND, SMT, 3020, Sheieded, 1.0uH, 4.0A, 100KHz, 32mOhm", Current=4.0A, DC Resistance=32mOhm, Manufacturer=Wurth, Manufacturer Part Number=74438336010, Operating Temperature=-40C~125C, Test Frequency=100KHz, TOLERANCE=20%
L10: library part CMP-FB-505-00014-1.1, "FB, SMT, 0402, 220 Ohm @ 100MHz, 500~700mA, 0.28 Ohm", Current="@85C/ 700mA; @125C/ 500mA", DC Resistance="0.28 Ohm", Impedance@Frequency="220 Ohm @ 100MHz", Manufacturer=Murata, Manufacturer Part Number=BLM15EG221SN1#, Operating Temperature=-55C~125C
L11 L12: library part CMP-IND-511-00094-1.2, "IND, SMT, 3225, Choke Coil,100uH, 150mA, +50% / -30%, 2.5 Ohm", Current=150mA, DC Resistance="2.5 Ohm", Manufacturer=Sunlord, Manufacturer Part Number=AMCW3225F-2-101T, Operating Temperature=-40C~150C, TOLERANCE="+50%/ -30%"
L14: library part CMP-IND-511-00168-1.2, "IND, SMT, 2016, Power Inductor, 2.2uH, 2.2A, 20%, 1MHz, 117 mOhm", Current=2.2A, DC Resistance="117 mOhm", Manufacturer=INPAQ, Manufacturer Part Number=WIP201610S-2R2MLDG, Operating Temperature=-40C~125C, Test Frequency=1MHz, TOLERANCE=20%
LED1 LED4: library part CMP-LED-521-00006-1.10, "LED, SMT, 0402, Red, 2.05V, 5mA, 45 mcd, 120 deg.", Alt. Manufacturer=Everlight, Alt. Manufacturer Part Number=16-219A/R6C-AM1N2BY/3T, Color=Red, Current=5mA, Manufacturer Part Number=EAST10052RA1, Operating Temperature=-40C~85C
LED2 LED3 LED5: library part CMP-LED-521-00015-1.2, "LED, SMT, 0603, Orange, 1.8V, 30mA, 50mcd, 120 deg.", Color=Orange, Current=30mA, Manufacturer=Kingbright, Manufacturer Part Number=APT1608LSECK/J4-PRV, Operating Temperature=-40C~85C
LED8 LED10: library part CMP-LED-521-00001-1.10, "LED, SMT, 0603, Green, 2.1V, 20mA, 50mcd, 120 deg.", Color=Green, Current=20mA, Manufacturer=Kingbright, Manufacturer Part Number=APG1608CGKC/T, Operating Temperature=-40C~85C
MH1: library part CMP-MSC-522-00003-1.2, "MSC, PEM Standoff, SMT, M2, 2.0mm Dia, 2.48mm Height", Manufacturer=Alink, Manufacturer Part Number=N0255520A1
MH2 MH5 MH8 MH11: library part CMP-MSC-522-00017-1.1, "MSC, Mounting Hole, Hole 1.524mm, Dia 1.524mm"
MH3 MH4 MH6 MH7 MH9 MH10 MH12 MH13: library part CMP-MSC-522-00015-1.2, "MSC, Mounting Hole, Hole 3.2mm, Dia 6mm"
MH14 MH15: library part CMP-MSC-522-00072-1.0, "MSC, PEM Standoff, TH, M2, 2.0mm Dia, 5.5mm Height 4.0mm", Manufacturer=EMISTOP, Manufacturer Part Number=F40M20-401126D4BM
Q1 Q2 Q3 Q4: library part CMP-FET-506-00015-1.2, "FET, SMT, SON8, N-Channel, 30V, 21A, 3.9 Ohm, 1.3Vgs", Current (Max)="21 A", Manufacturer=TI, Manufacturer Part Number=CSD17581Q3A, Operating Temperature=-55C~150C, Power Max (W)="63 W"
Q5 Q6 Q7 Q8 Q10 Q13 Q14 Q15 Q20 Q21: library part CMP-FET-506-00017-1.3, "FET, SMT, SOT23, N-Channel, 20V, 5A, 32 mOhm, 1Vgs max", Current (Max)=5A, Manufacturer=SECOS, Manufacturer Part Number=SMS2312, Operating Temperature=-55C~150C, Power Max (W)=1.4W
Q16: library part CMP-FET-506-00003-1.11, "FET, SMT, SOT23, P-Channel, 20v, 2A, 70 mOhm, 8Vgs max", Current (Max)=2A, Manufacturer="ON Semiconductor", Manufacturer Part Number=FDN340P, Operating Temperature=-55C~150C, Power Max (W)=500mW
Q17 Q18 Q19: library part CMP-FET-506-00016-1.2, "FET, SMT, SOT523, N-Channel, 20V, 450mA, 0.7 Ohm, 6Vgs max", Current (Max)=450mA, Manufacturer=Diodes, Manufacturer Part Number=DMG1012T-7, Operating Temperature=-55C~150C, Power Max (W)=0.28W
R1 R5 R12 R50 R144 R176 R203 R207 R208 R222 R223 R224 R225 R244 R274 R276 R318 R415 R418 R419 R432 R526 R530 R537: library part CMP-RES-514-00021-1.23, "RES, SMT, 0402, Thick Film, 0, 0.0625W", Alt. Manufacturer=Any, Manufacturer=Yageo, Manufacturer Part Number=RC0402FR-070RL, Operating Temperature=-55C~155C, Power=0.0625W, TOLERANCE=NA
R2 R10 R75 R204 R239: library part CMP-RES-514-00051-1.18, "RES, SMT, 0402, Thick Film, 2.2k, 5%, 0.0625W", Alt. Manufacturer=Any, Manufacturer=Yageo, Manufacturer Part Number=RC0402JR-072K2L, Operating Temperature=-55C~125C, Power=0.0625W, TOLERANCE=5%
R3: library part CMP-RES-514-00170-1.9, "RES, SMT, 0402, Thick Film, 36.5k, 1%, 0.0625W", Alt. Manufacturer=Any, Manufacturer=Yageo, Manufacturer Part Number=RC0402FR-0736K5L, Operating Temperature=-55C~155C, Power=0.0625W, TOLERANCE=1%
R4 R9 R199 R252: library part CMP-RES-514-00052-1.18, "RES, SMT, 0402, Thick Film, 4.99k, 1%, 0.0625W", Alt. Manufacturer=Any, Manufacturer=Yageo, Manufacturer Part Number=RC0402FR-074K99L, Operating Temperature=-55C~155C, Power=0.0625W, TOLERANCE=1%
R6 R7 R11 R15 R67 R68 R233 R320 R321 R323 R324: library part CMP-RES-514-00061-1.17, "RES, SMT, 0402, Thick Film, 10.0k, 1%, 0.0625W", Alt. Manufacturer=Any, Manufacturer=Yageo, Manufacturer Part Number=RC0402FR-0710KL, Operating Temperature=-55C~155C, Power=0.0625W, TOLERANCE=1%
R8: library part CMP-RES-514-00171-1.10, "RES, SMT, 0402, Thick Film, 22.6k, 1%, 0.0625W", Alt. Manufacturer=Any, Manufacturer=Yageo, Manufacturer Part Number=RC0402FR-0722K6L, Operating Temperature=-55C~155C, Power=0.0625W, TOLERANCE=1%
R13: library part CMP-RES-514-00038-1.19, "RES, SMT, 0402, Thick Film, 100, 5%, 0.0625W", Alt. Manufacturer=Any, Manufacturer=Yageo, Manufacturer Part Number=RC0402JR-07100RL, Operating Temperature=-55C~125C, Power=0.0625W, TOLERANCE=5%
R14: library part CMP-RES-514-00058-1.15, "RES, SMT, 0402, Thick Film, 20k, 1%, 0.0625W", Alt. Manufacturer=Any, Manufacturer=Yageo, Manufacturer Part Number=RC0402FR-0720KL, Operating Temperature=-55C~125C, Power=0.0625W, TOLERANCE=1%
R16 R17 R27 R31 R37 R43 R49 R52 R53 R55 R56 R61 R62 R76 R77 R87 R91 R109 R110 R120 R124 R145 R146 R189 R190 R192 R194 R195 R201 R209 R210 R234 R236 R237 R238 R240 R241 R242 R243 R245 R246 R247 R249 R250 R251 R254 R255 R263 R264 R265 R266 R267 R268 R269 R270 R273 R278 R280 R281 R283 R298 R300 R302 R304 R305 R306 R307 R308 R309 R310 R311 R312 R313 R314 R315 R316 R317 R319 R325 R328 R329 R332 R333 R334 R335 R336 R337 R339 R340 R341 R342 R344 R345 R350 R351 R355 R357 R358 R362 R364 R365 R367 R368 R369 R370 R379 R380 R381 R382 R401 R402 R403 R404 R405 R411 R425 R431 R440 R443 R462 R467 R468 R469 R470 R471 R478 R479 R480 R484 R485 R489 R490 R493 R494 R498 R499 R503 R504 R508 R509 R510 R511 R512 R513 R514 R517 R555 R556 R567 R573 R575 R576 R577 R579 R581 R582 R583 R585 R587 R588 R589 R590 R593 R594 R595 R596 R607 R608: library part CMP-RES-514-00004-1.33, "RES, SMT, 0201, Thick Film, 0, 0.05W", Alt. Manufacturer=Any, Manufacturer=Yageo, Manufacturer Part Number=RC0201JR-070RL, Operating Temperature=-55C~125C, Power=0.05W, TOLERANCE=NA
R18 R177 R178 R179 R180 R181 R182: library part CMP-RES-514-00207-1.5, "RES, SMT, 0603, Thick Film, 0", Alt. Manufacturer=Any, Manufacturer="KOA Speer", Manufacturer Part Number=RK73Z1JTTD, Operating Temperature=-55C~155C, Power=., TOLERANCE=0
R19 R24 R25 R29: library part CMP-RES-514-00257-1.3, "RES, SMT, 0201, Thick Film, 12, 5%, 0.05W", Alt. Manufacturer=Any, Manufacturer=Yageo, Manufacturer Part Number=RC0201JR-0712RL, Operating Temperature=-55C~125C, Power=0.05W, TOLERANCE=5%
R20 R21 R196 R197 R279 R286 R288 R289 R290 R293 R294 R299 R347 R354 R356 R361 R363 R428 R491 R492 R495 R496 R500 R501 R505 R506: library part CMP-RES-514-00123-1.15, "RES, SMT, 0201, Thick Film, 4.7k, 5%, 0.05W", Alt. Manufacturer=Any, Manufacturer=Yageo, Manufacturer Part Number=RC0201JR-074K7P, Operating Temperature=-55C~125C, Power=0.05W, TOLERANCE=5%
R22 R23: library part CMP-RES-514-00177-1.7, "RES, SMT, 2512, Thick Film, 0.033, 1%, 1W", Manufacturer=Vishay, Manufacturer Part Number=WSL2512R0330FEA, Operating Temperature=-65C~170C, Power=1W, TOLERANCE=1%
R26 R32 R34 R36 R46 R47 R48 R51 R57 R58 R59 R60 R143 R152 R157 R159 R160 R161 R164 R167 R172 R174 R175 R187 R191 R221 R228 R229 R230 R235 R259 R262 R287 R291 R292 R295 R303 R327 R330 R331 R348 R349 R352 R359 R360 R371 R372 R373 R374 R375 R376 R383 R384 R385 R386 R387 R388 R389 R390 R391 R392 R395 R397 R398 R400 R416 R427 R437 R444 R445 R446 R447 R448 R449 R465 R466 R472 R473 R474 R483 R488 R497 R502 R507 R515 R516 R518 R522 R523 R538 R539 R540 R541 R542 R543 R544 R545 R546 R564 R565 R570 R571 R606: library part CMP-RES-514-00098-1.18, "RES, SMT, 0201, Thick Film, 10k, 5%, 0.05W", Alt. Manufacturer=Any, Manufacturer=Yageo, Manufacturer Part Number=RC0201JR-0710KL, Operating Temperature=-55C~125C, Power=0.05W, TOLERANCE=5%
R28: library part CMP-RES-514-00272-1.5, "RES, SMT, 0402, Thick Film, 52.3k, 1%, 0.0625W", Alt. Manufacturer=Any, Manufacturer=Yageo, Manufacturer Part Number=RC0402FR-0752K3L, Operating Temperature=-55C~155C, Power=0.0625W, TOLERANCE=1%
R30 R35 R40 R45: library part CMP-RES-514-00274-1.5, "RES, SMT, 0402, Thick Film, 9.76k, 1%, 0.0625W", Alt. Manufacturer=Any, Manufacturer=Yageo, Manufacturer Part Number=RC0402FR-079K76L, Operating Temperature=-55C~155C, Power=0.0625W, TOLERANCE=1%
R33: library part CMP-RES-514-00348-1.3, "RES, SMT, 0402, Thick Film, 30.9k, 1%, 0.0625W", Alt. Manufacturer=Any, Manufacturer=Yageo, Manufacturer Part Number=RT0402FRE0730K9L, Operating Temperature=-55C~155C, Power=0.0625W, TOLERANCE=1%
R38: library part CMP-RES-514-00035-1.19, "RES, SMT, 0402, Thick Film, 12.4k, 1%, 0.0625W", Alt. Manufacturer=Any, Manufacturer=Yageo, Manufacturer Part Number=RC0402FR-0712K4L, Operating Temperature=-55C~155C, Power=0.0625W, TOLERANCE=1%
R39 R41 R42 R451: library part CMP-RES-514-00093-1.14, "RES, SMT, 0402, Thick Film, 15k, 5%, 0.0625W", Alt. Manufacturer=Any, Manufacturer=Yageo, Manufacturer Part Number=RC0402JR-0715KL, Operating Temperature=-55C~155C, Power=0.0625W, TOLERANCE=5%
R44: library part CMP-RES-514-00346-1.4, "RES, SMT, 0402, Thick Film, 21k, 1%, 0.0625W", Alt. Manufacturer=Any, Manufacturer=Yageo, Manufacturer Part Number=RT0402FRE0721KL, Operating Temperature=-55C~155C, Power=0.0625W, TOLERANCE=1%
R54: library part CMP-RES-514-00334-1.3, "RES, SMT, 0402, Thick Film, 3.48, 1%, 0.0625W", Alt. Manufacturer=Any, Manufacturer=Yageo, Manufacturer Part Number=RC0402FR-073R48L, Operating Temperature=-55C~155C, Power=0.0625W, TOLERANCE=1%
R63 R64 R78 R79 R111 R112 R211 R212 R213 R214 R215 R216 R217 R218 R219 R220 R394 R399 R435 R436 R452 R453 R454 R455 R456 R457 R458 R459 R460 R461 R463 R464 R481 R482 R486 R487 R520 R521 R533 R534 R535: library part CMP-RES-514-00148-1.14, "RES, SMT, 0201, Thick Film, 2.2k, 5%, 0.05W", Alt. Manufacturer=Any, Manufacturer=Yageo, Manufacturer Part Number=RC0201JR-072K2L, Operating Temperature=-55C~125C, Power=0.05W, TOLERANCE=5%
R65 R66: library part CMP-RES-514-00166-1.4, "RES, SMT, 0603, Thick Film, 294, 1%, 0.1W", Alt. Manufacturer=Any, Manufacturer="Vishay Dale", Manufacturer Part Number=CRCW0603294RFKEA, Operating Temperature=-55C~155C, Power=0.1W, TOLERANCE=1%
R69: library part CMP-RES-514-00167-1.9, "RES, SMT, 0402, Thick Film, 5.23k, 1%, 0.0625W", Alt. Manufacturer=Any, Manufacturer=Yageo, Manufacturer Part Number=RC0402FR-075K23L, Operating Temperature=-55C~155C, Power=0.0625W, TOLERANCE=1%
R70: library part CMP-RES-514-00132-1.12, "RES, SMT, 0402, Thick Film, 56k, 1%, 0.0625W", Alt. Manufacturer=Any, Manufacturer=Yageo, Manufacturer Part Number=RC0402FR-0756KL, Operating Temperature=-55C~155C, Power=0.0625W, TOLERANCE=1%
R71 R574: library part CMP-RES-514-00168-1.9, "RES, SMT, 0402, Thick Film, 30.1k, 1%, 0.0625W", Alt. Manufacturer=Any, Manufacturer=Yageo, Manufacturer Part Number=RC0402FR-0730K1L, Operating Temperature=-55C~155C, Power=0.0625W, TOLERANCE=1%
R72 R206 R301 R410: library part CMP-RES-514-00070-1.16, "RES, SMT, 0402, Thick Film, 100k, 1%, 0.0625W", Alt. Manufacturer=Any, Manufacturer=Yageo, Manufacturer Part Number=RC0402FR-07100KL, Operating Temperature=-55C~125C, Power=0.0625W, TOLERANCE=1%
R73: library part CMP-RES-514-00113-1.7, "RES, SMT, 0603, Thick Film, 100, 1%, 0.125W", Alt. Manufacturer=Any, Manufacturer=KOA, Manufacturer Part Number=RK73H1JTTD1000F, Operating Temperature=-55C~125C, Power=0.125W, TOLERANCE=1%
R74 R93 R95 R96 R98 R99 R100 R126 R128 R129 R131 R132 R133: library part CMP-RES-514-00040-1.20, "RES, SMT, 0201, Thick Film, 6.04k, 1%, 0.05W", Alt. Manufacturer=Any, Manufacturer=Yageo, Manufacturer Part Number=RC0201FR-076K04L, Operating Temperature=-55C~125C, Power=0.05W, TOLERANCE=1%
R80 R83 R84 R86 R88 R89 R113 R116 R117 R119 R121 R122 R183 R184 R185 R186: library part CMP-RES-514-00082-1.21, "RES, SMT, 0201, Thick Film, 27, 1%,0.05W,", Alt. Manufacturer=Any, Manufacturer=Yageo, Manufacturer Part Number=RC0201FR-0727RL, Operating Temperature=-55C~125C, Power=0.05W, TOLERANCE=1%
R81 R85 R114 R118: library part CMP-RES-514-00106-1.17, "RES, SMT, 0201, Thick Film, 100, 1%, 0.05W", Alt. Manufacturer=Any, Manufacturer=Yageo, Manufacturer Part Number=RC0201FR-07100RL, Operating Temperature=-55C~125C, Power=0.05W, TOLERANCE=1%
R82 R115: library part CMP-RES-514-00027-1.13, "RES, SMT, 1206, Thick Film, 1M, 5%, 0.25W", Alt. Manufacturer=Any, Manufacturer=Yageo, Manufacturer Part Number=RC1206JR-071ML, Operating Temperature=-55C~155C, Power=0.25W, TOLERANCE=5%
R90 R94 R123 R127 R130: library part CMP-RES-514-00142-1.16, "RES, SMT, 0201, Thick Film, 11k, 1%, 0.05W", Alt. Manufacturer=Any, Manufacturer=Yageo, Manufacturer Part Number=RC0201FR-0711KL, Operating Temperature=-55C~125C, Power=0.05W, TOLERANCE=1%
R92 R125: library part CMP-RES-514-00017-1.29, "RES, SMT, 0201, Thick Film, 1M, 1%, 0.05W", Alt. Manufacturer=Any, Manufacturer=Yageo, Manufacturer Part Number=RC0201FR-071ML, Operating Temperature=-55C~125C, Power=0.05W, TOLERANCE=1%
R97 R101 R102 R103 R104 R105 R106 R107 R108 R134 R135 R136 R137 R138 R139 R140 R141: library part CMP-RES-514-00138-1.15, "RES, SMT, 0201, Thick Film, 2.49k, 1%, 0.05W", Alt. Manufacturer=Any, Manufacturer=Yageo, Manufacturer Part Number=RC0201FR-072K49L, Operating Temperature=-55C~125C, Power=0.05W, TOLERANCE=1%
R142 R158 R173 R198 R202 R441 R547 R548 R549 R550 R551 R552 R553 R554: library part CMP-RES-514-00184-1.9, "RES, SMT, 0201, Thick Film, 100k, 5%, 0.05W", Alt. Manufacturer=Any, Manufacturer=Walsin, Manufacturer Part Number=WR02X104JAL, Operating Temperature=-55C~125C, Power=0.05W, TOLERANCE=5%
R147 R155 R156 R162 R170 R171 R256 R257 R258 R261 R296 R297 R429 R430 R433 R475 R476 R477 R557 R558 R566: library part CMP-RES-514-00172-1.9, "RES, SMT, 0201, Thick Film, 1.0k, 5%, 0.05W", Alt. Manufacturer=Any, Manufacturer=YAGEO, Manufacturer Part Number=RC0201JR-071KL, Operating Temperature=-55C~125C, Power=0.05W, TOLERANCE=5%
R148 R163 R559: library part CMP-RES-514-00335-1.3, "RES, SMT, 0402, Thick Film, 909k, 1%, 0.0625W", Alt. Manufacturer=Any, Manufacturer=Yageo, Manufacturer Part Number=RC0402FR-07909KL, Operating Temperature=-55C~155C, Power=0.0625W, TOLERANCE=1%
R149 R417 R420 R421 R422 R423 R424 R442 R450 R527 R529 R532: library part CMP-RES-514-00260-1.2, "RES, SMT, 0201, Thick Film, 47k, 1%, 0.05W", Alt. Manufacturer=Any, Manufacturer=Yageo, Manufacturer Part Number=RC0201FR-0747KL, Operating Temperature=-55C~125C, Power=0.05W, TOLERANCE=1%
R150 R151 R153 R154 R165 R166 R168 R169 R285 R353 R377 R378 R519 R560 R561 R562 R563: library part CMP-RES-514-00255-1.2, "RES, SMT, 0201, Thick Film, 200k, 1%, 0.05W", Alt. Manufacturer=Any, Manufacturer=Walsin, Manufacturer Part Number=WR02X2003FAL, Operating Temperature=-55C~125C, Power=0.05W, TOLERANCE=1%
R188: library part CMP-RES-514-00182-1.10, "RES, SMT, 0402, Thick Film, 330k, 1%, 0.0625W", Alt. Manufacturer=Any, Manufacturer=Yageo, Manufacturer Part Number=RC0402FR-07330KL, Operating Temperature=-55C~155C, Power=0.0625W, TOLERANCE=1%
R193 R200 R600 R601: library part CMP-RES-514-00227-1.9, "RES, SMT, 0402, Thick Film, 68.1k, 1%, 0.0625W", Alt. Manufacturer=Any, Manufacturer=Yageo, Manufacturer Part Number=RC0402FR-0768K1L, Operating Temperature=-55C~155C, Power=0.0625W, TOLERANCE=1%
R205: library part CMP-RES-514-00154-1.13, "RES, SMT, 0402, Thick Film, 47k, 1%, 0.0625W", Alt. Manufacturer=Any, Manufacturer=Yageo, Manufacturer Part Number=RC0402FR-0747KL, Operating Temperature=-55C~155C, Power=0.0625W, TOLERANCE=1%
R226 R227 R232 R248 R322 R366 R393 R396 R406 R407 R409 R412 R426 R434 R528 R578 R580 R584 R586 R591 R592 R597 R598: library part CMP-RES-514-00124-1.16, "RES, SMT, 0201, Thick Film, 49.9k, 1%, 0.05W", Alt. Manufacturer=Any, Manufacturer=Yageo, Manufacturer Part Number=RC0201FR-0749K9L, Operating Temperature=-55C~125C, Power=0.05W, TOLERANCE=1%
R231: library part CMP-RES-514-00147-1.14, "RES, SMT, 0402, Thick Film, 66.5k, 1%, 0.0625W", Alt. Manufacturer=Any, Manufacturer=Yageo, Manufacturer Part Number=RC0402FR-0766K5L, Operating Temperature=-55C~155C, Power=0.0625W, TOLERANCE=1%
R253 R271: library part CMP-RES-514-00078-1.13, "RES, SMT, 0402, Thick Film, 30k, 1%, 0.0625W", Alt. Manufacturer=Any, Manufacturer=Yageo, Manufacturer Part Number=RC0402FR-0730KL, Operating Temperature=-55C~155C, Power=0.0625W, TOLERANCE=1%
R260 R272: library part CMP-RES-514-00225-1.8, "RES, SMT, 0402, Thick Film, 27.4k, 1%, 0.0625W", Alt. Manufacturer=Any, Manufacturer=Yageo, Manufacturer Part Number=RC0402FR-0727K4L, Operating Temperature=-55C~155C, Power=0.0625W, TOLERANCE=1%
R275 R277 R282 R284: library part CMP-RES-514-00178-1.4, "RES, SMT, 0603, Thick Film, 60.4, 1%, 100mW", Alt. Manufacturer=Any, Manufacturer=Yageo, Manufacturer Part Number=RC0603FR-0760R4L, Operating Temperature=-55C~155C, Power="100 mW", TOLERANCE=1%
R326: library part CMP-RES-514-00024-1.22, "RES, SMT, 0201, Thick Film, 174k, 1%, 0.05W", Alt. Manufacturer=Any, Manufacturer=Yageo, Manufacturer Part Number=RC0201FR-07174KL, Operating Temperature=-55C~125C, Power=0.05W, TOLERANCE=1%
R338 R343: library part CMP-RES-514-00064-1.26, "RES, SMT, 0201, Thick Film, 100k, 1%, 0.05W", Alt. Manufacturer=Any, Manufacturer=Yageo, Manufacturer Part Number=RC0201FR-07100KL, Operating Temperature=-55C~125C, Power=0.05W, TOLERANCE=1%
